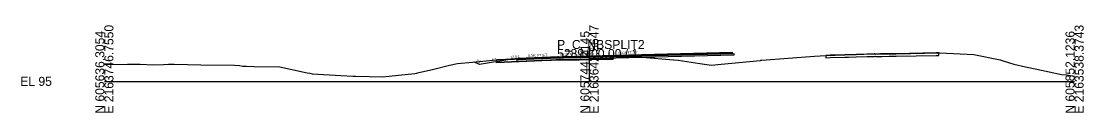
# Model space of a CAD drawing. Extents: x -26 to 1303, y -10 to 12038.
# Drawn here: x -25.7 to 302.8, y 4990.3 to 5017.3 of the extents above; entities that cross this region are included whole.
import ezdxf

# ---------------------------------------------------------------- set-up
doc = ezdxf.new("R2010")
doc.units = 0
for name, color, linetype in [('RD_GPK_XS_Cell', 7, 'Continuous'), ('RD_XS_Base', 7, 'Continuous'), ('RD_XS_ExGround', 7, 'Continuous'), ('RD_XS_ExPaveRet', 7, 'Continuous'), ('RD_XS_Greenside', 7, 'Continuous'), ('RD_XS_Pave', 7, 'Continuous'), ('RD_XS_PaveOvlay_CP', 7, 'Continuous'), ('RD_XS_TieSlope', 7, 'Continuous'), ('RD_XS_TX_Elev_EX', 7, 'Continuous'), ('RD_XS_TX_Elev_PR', 7, 'Continuous'), ('RD_XS_TX_ShdSlope', 7, 'Continuous'), ('RD_XS_TX_Slope', 7, 'Continuous')]:
    doc.layers.add(name, color=color, linetype=linetype)

msp = doc.modelspace()

# ---------------------------------------------------------------- linework, layer by layer
at = {"layer": 'RD_GPK_XS_Cell'}
for p, q in [((150, 5000), (150, 5010)), ((0, 5000), (150, 5000)), ((150, 5000), (300, 5000))]:
    msp.add_line(p, q, dxfattribs=at)
at = {"layer": 'RD_XS_Base'}
for p, q in [((138, 5007.13), (128, 5006.73)), ((150, 5007.45), (138, 5007.13)), ((138, 5007.13), (138, 5007.13)), ((138, 5006.63), (150, 5006.95)), ((150, 5007.45), (194.69, 5008.61)), ((194.69, 5008.11), (150, 5006.95)), ((150, 5006.95), (150, 5007.6)), ((150, 5007.6), (150, 5007.6)), ((150, 5007.6), (150, 5007.6)), ((150, 5007.6), (150, 5007.45)), ((150, 5007.45), (150, 5007.45)), ((150, 5006.95), (150, 5007.45)), ((150, 5007.45), (150, 5007.45)), ((150, 5007.45), (150, 5007.45)), ((150, 5006.95), (150, 5006.95)), ((174, 5008.07), (174, 5008.07)), ((174, 5008.07), (174, 5008.07)), ((174, 5007.57), (174, 5007.57)), ((174, 5007.57), (174, 5007.57)), ((194.19, 5008.59), (194.19, 5008.59)), ((194.69, 5008.61), (194.69, 5008.11)), ((194.69, 5008.57), (194.69, 5008.57)), ((128, 5006.73), (127.5, 5006.71)), ((127.5, 5006.71), (127.5, 5006.71)), ((127.5, 5006.71), (127.5, 5006.21)), ((127.5, 5006.21), (128, 5006.23)), ((128, 5006.73), (128, 5006.73)), ((128, 5006.23), (138, 5006.63)), ((128, 5006.23), (128, 5006.23)), ((138, 5006.63), (138, 5006.63))]:
    msp.add_line(p, q, dxfattribs=at)
at = {"layer": 'RD_XS_ExGround'}
msp.add_lwpolyline([(0, 5005.17), (7.18, 5005.32), (8.03, 5005.36), (9.68, 5005.34), (11.05, 5005.3), (15.07, 5005.15), (18.25, 5005.24), (19.8, 5005.28), (20.27, 5005.27), (20.56, 5005.28), (21.62, 5005.29), (29.84, 5005.15), (40.27, 5004.97), (41.77, 5004.89), (42.75, 5004.75), (43.37, 5004.69), (43.51, 5004.68), (43.96, 5004.66), (46.19, 5004.63), (54.22, 5004.52), (62.73, 5002.67), (63.5, 5002.51), (64.28, 5002.33), (73.11, 5001.83), (76.97, 5001.6), (77.78, 5001.59), (86.08, 5001.42), (91, 5001.93), (96.04, 5002.48), (96.59, 5002.54), (96.67, 5002.56), (96.81, 5002.59), (101.89, 5003.82), (106.72, 5005.03), (109.18, 5005.52), (113.81, 5005.92), (121.27, 5006.61), (135.26, 5007.18), (138.28, 5007.33), (139.71, 5007.36), (141.03, 5007.37), (141.35, 5007.36), (142.4, 5007.39), (144.61, 5007.45), (146.84, 5007.46), (148.45, 5007.5), (150.25, 5007.51), (157.31, 5007.66), (161.06, 5007.6), (163.24, 5007.55), (165.89, 5007.5), (166.43, 5007.49), (175.99, 5006.68), (177.47, 5006.51), (184.13, 5005.52), (187.7, 5005.01), (190.71, 5005.35), (202.79, 5006.5), (202.91, 5006.5), (203.02, 5006.51), (203.25, 5006.53), (219.58, 5007.82), (223.06, 5008.05), (229.01, 5008.21), (232.45, 5008.31), (237.2, 5008.47), (238.11, 5008.5), (238.15, 5008.5), (238.25, 5008.5), (238.58, 5008.44), (239.97, 5008.47), (242.48, 5008.5), (242.79, 5008.51), (244.82, 5008.54), (258.03, 5008.79), (258.35, 5008.78), (268.88, 5008.32), (277.01, 5006.61), (277.57, 5006.49), (279.87, 5005.73), (281.22, 5005.34), (284.84, 5004.5), (288.37, 5003.78), (296, 5002.15), (297.52, 5002.01), (300, 5001.58)], dxfattribs=at)
at = {"layer": 'RD_XS_ExPaveRet'}
for points in [[(157.31, 5007.66), (157.31, 5007.66), (157.31, 5006.91), (157.31, 5006.91), (157.31, 5006.91), (150.25, 5006.76), (150.25, 5006.76), (148.45, 5006.75), (146.84, 5006.71), (146.84, 5006.71), (146.84, 5006.71), (144.61, 5006.7), (144.61, 5006.7), (142.4, 5006.64), (142.4, 5006.64), (141.35, 5006.61), (141.03, 5006.62), (141.03, 5006.62), (141.03, 5006.62), (139.71, 5006.61), (138.28, 5006.58), (138.28, 5006.58), (135.26, 5006.43), (135.26, 5006.43), (121.27, 5005.86), (121.27, 5005.86), (121.27, 5006.61), (121.27, 5006.61), (121.27, 5006.61), (135.26, 5007.18), (135.26, 5007.18), (138.28, 5007.33), (138.28, 5007.33), (139.71, 5007.36), (141.03, 5007.37), (141.03, 5007.37), (141.03, 5007.37), (141.35, 5007.36), (142.4, 5007.39), (142.4, 5007.39), (144.61, 5007.45), (144.61, 5007.45), (146.84, 5007.46), (146.84, 5007.46), (146.84, 5007.46), (148.45, 5007.5), (150.25, 5007.51), (150.25, 5007.51), (157.31, 5007.66), (157.31, 5007.66), (157.31, 5007.66)], [(157.31, 5007.66), (150.25, 5007.51), (148.45, 5007.5), (146.84, 5007.46), (144.61, 5007.45), (142.4, 5007.39), (141.35, 5007.36), (141.03, 5007.37), (139.71, 5007.36), (138.28, 5007.33), (135.26, 5007.18), (121.27, 5006.61), (121.27, 5005.86), (135.26, 5006.43), (138.28, 5006.58), (139.71, 5006.61), (141.03, 5006.62), (141.35, 5006.61), (142.4, 5006.64), (144.61, 5006.7), (146.84, 5006.71), (148.45, 5006.75), (150.25, 5006.76), (157.31, 5006.91), (157.31, 5006.91), (157.31, 5007.66), (157.31, 5007.66)], [(258.03, 5008.79), (258.01, 5008.79), (257.21, 5008.78), (244.82, 5008.54), (243.75, 5008.53), (242.79, 5008.51), (242.65, 5008.5), (240.42, 5008.48), (240.23, 5008.47), (239.97, 5008.47), (238.73, 5008.44), (238.58, 5008.44), (238.52, 5008.45), (238.26, 5008.5), (238.16, 5008.49), (238.11, 5008.49), (238, 5008.49), (237.03, 5008.46), (235.89, 5008.42), (232.45, 5008.31), (230.11, 5008.25), (229.01, 5008.21), (224.39, 5008.08), (223.06, 5008.05), (223.06, 5007.51), (223.06, 5007.3), (224.39, 5007.33), (229.01, 5007.46), (230.11, 5007.5), (232.45, 5007.56), (235.89, 5007.67), (237.03, 5007.71), (238, 5007.74), (238.11, 5007.74), (238.16, 5007.74), (238.26, 5007.75), (238.52, 5007.7), (238.58, 5007.69), (238.73, 5007.69), (239.97, 5007.72), (240.23, 5007.72), (240.42, 5007.73), (242.65, 5007.75), (242.79, 5007.76), (243.75, 5007.78), (244.82, 5007.79), (257.21, 5008.03), (258.01, 5008.04), (258.03, 5008.04), (258.03, 5008.04), (258.03, 5008.74), (258.03, 5008.79), (258.03, 5008.79)], [(258.03, 5008.79), (258.01, 5008.79), (257.21, 5008.78), (244.82, 5008.54), (243.75, 5008.53), (242.79, 5008.51), (242.65, 5008.5), (240.42, 5008.48), (240.23, 5008.47), (239.97, 5008.47), (238.73, 5008.44), (238.58, 5008.44), (238.52, 5008.45), (238.26, 5008.5), (238.16, 5008.49), (238.11, 5008.49), (238, 5008.49), (237.03, 5008.46), (235.89, 5008.42), (232.45, 5008.31), (230.11, 5008.25), (229.01, 5008.21), (224.39, 5008.08), (223.06, 5008.05), (223.06, 5007.51), (223.06, 5007.3), (224.39, 5007.33), (229.01, 5007.46), (230.11, 5007.5), (232.45, 5007.56), (235.89, 5007.67), (237.03, 5007.71), (238, 5007.74), (238.11, 5007.74), (238.16, 5007.74), (238.26, 5007.75), (238.52, 5007.7), (238.58, 5007.69), (238.73, 5007.69), (239.97, 5007.72), (240.23, 5007.72), (240.42, 5007.73), (242.65, 5007.75), (242.79, 5007.76), (243.75, 5007.78), (244.82, 5007.79), (257.21, 5008.03), (258.01, 5008.04), (258.03, 5008.04), (258.03, 5008.04), (258.03, 5008.74), (258.03, 5008.79), (258.03, 5008.79)]]:
    msp.add_lwpolyline(points, dxfattribs=at)
at = {"layer": 'RD_XS_Greenside'}
for p, q in [((126, 5006.89), (116, 5005.22)), ((116, 5005.22), (114.48, 5005.98))]:
    msp.add_line(p, q, dxfattribs=at)
at = {"layer": 'RD_XS_Pave'}
for p, q in [((138, 5007.45), (128, 5007.05)), ((128, 5006.89), (138, 5007.29)), ((138, 5007.29), (128, 5006.89)), ((128, 5006.73), (138, 5007.13)), ((128, 5007.05), (128, 5007.05)), ((128, 5007.05), (128, 5006.89)), ((128, 5006.89), (128, 5006.89)), ((128, 5006.89), (128, 5006.73)), ((150, 5007.76), (138, 5007.45)), ((138, 5007.29), (150, 5007.6)), ((150, 5007.6), (138, 5007.29)), ((138, 5007.45), (138, 5007.45)), ((138, 5007.13), (150, 5007.45)), ((138, 5007.29), (138, 5007.29)), ((138, 5007.29), (138, 5007.29)), ((138, 5007.13), (138, 5007.13)), ((194.19, 5008.91), (150, 5007.76)), ((194.19, 5008.75), (150, 5007.6)), ((150, 5007.6), (194.19, 5008.75)), ((150, 5007.45), (194.19, 5008.59)), ((150, 5007.76), (150, 5007.76)), ((150, 5007.6), (150, 5007.6)), ((150, 5007.6), (150, 5007.6)), ((150, 5007.6), (150, 5007.45)), ((150, 5007.6), (150, 5007.6)), ((150, 5007.45), (150, 5007.6)), ((150, 5007.6), (150, 5007.6)), ((150, 5007.6), (150, 5007.6)), ((150, 5007.45), (150, 5007.45)), ((150, 5007.45), (150, 5007.45)), ((174, 5008.39), (174, 5008.39)), ((174, 5008.39), (174, 5008.39)), ((174, 5008.23), (174, 5008.23)), ((174, 5008.23), (174, 5008.23)), ((174, 5008.23), (174, 5008.23)), ((174, 5008.23), (174, 5008.23)), ((174, 5008.07), (174, 5008.07)), ((174, 5008.07), (174, 5008.07)), ((194.19, 5008.75), (194.19, 5008.91)), ((194.19, 5008.91), (194.19, 5008.91)), ((194.19, 5008.59), (194.19, 5008.75)), ((194.19, 5008.75), (194.19, 5008.75))]:
    msp.add_line(p, q, dxfattribs=at)
at = {"layer": 'RD_XS_PaveOvlay_CP'}
for p, q in [((138, 5007.45), (128, 5007.05)), ((150, 5007.76), (138, 5007.45)), ((138, 5007.45), (138, 5007.45)), ((194.19, 5008.91), (150, 5007.76)), ((150, 5007.76), (150, 5007.76)), ((174, 5008.39), (174, 5008.39)), ((174, 5008.39), (174, 5008.39))]:
    msp.add_line(p, q, dxfattribs=at)
at = {"layer": 'RD_XS_TieSlope'}
msp.add_line((128, 5007.05), (126, 5006.89), dxfattribs=at)

# ---------------------------------------------------------------- texts
at = {"layer": 'RD_GPK_XS_Cell'}
for s, p in [('E 2163746.7550', (2.8, 4990)), ('E 2163642.5647', (152.8, 4990)), ('E 2163538.3743', (302.8, 4990)), ('N 605636.3054', (0, 4990)), ('N 605744.2145', (150, 4990)), ('N 605852.1236', (300, 4990))]:
    msp.add_text(s, height=2.8, rotation=90, dxfattribs=at).set_placement(p)
for s, p in [('5289+00.00 / 1', (140, 5007.2)), ('P_C_NBSPLIT2', (140, 5010)), ('EL 95', (-26, 4998.6))]:
    msp.add_text(s, height=2.8, dxfattribs=at).set_placement(p)
at = {"layer": 'RD_XS_TX_Elev_EX'}
msp.add_text('102.52', height=0.6, rotation=90, dxfattribs=at).set_placement((149.79, 5008.26))
at = {"layer": 'RD_XS_TX_Elev_PR'}
msp.add_text('102.76', height=1, rotation=90, dxfattribs=at).set_placement((151.2, 5008.07))
at = {"layer": 'RD_XS_TX_ShdSlope'}
msp.add_text('12.5:1', height=0.75, rotation=4.5739, dxfattribs=at).set_placement((125.59, 5007.12))
at = {"layer": 'RD_XS_TX_Slope'}
for s, rotation, p in [('6:1', 9.4642, (119.89, 5006.29)), ('0.040 FT./FT.', 2.2906, (130.99, 5007.56)), ('0.028 FT./FT.', 1.6039, (141, 5007.93)), ('0.028 FT./FT.', 1.6039, (159, 5008.43)), ('2:1', 333.4349, (114.93, 5006.22))]:
    msp.add_text(s, height=0.75, rotation=rotation, dxfattribs=at).set_placement(p)

doc.saveas('drawing.dxf')
